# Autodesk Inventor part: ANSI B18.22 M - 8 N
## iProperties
Comments: To add or edit properties for Autodesk Inventor files, use iProperties.
Created: 2004-07
Part Number: ANSI B18.22 M - 8 N
Vendor: Autodesk Inc.
Document SubType Name: Modeling
Designer: John Blackburn
Material: Default
Description: Plain Washer
Standard: ANSI B18.22 M
Size Designation: 8 N
Alert: To add or edit properties for Autodesk Inventor files, use iProperties.
Control State: 0
Master: False
Checked Out: False
Shininess: 64.0
Length Units: 11269
Angle Units: 11279
Time Units: 11290
Mass Units: 11283
Length Display Precision: 3
Angle Display Precision: 2
Compacted: True
Classification: un/spsc 31161807
Density: 0.0
Volumn: 0.0
Area: 0.0
PropertySet Name: Model Information
Author: John Blackburn
Revision Number: 8
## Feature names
1. Body [Extrusion]
